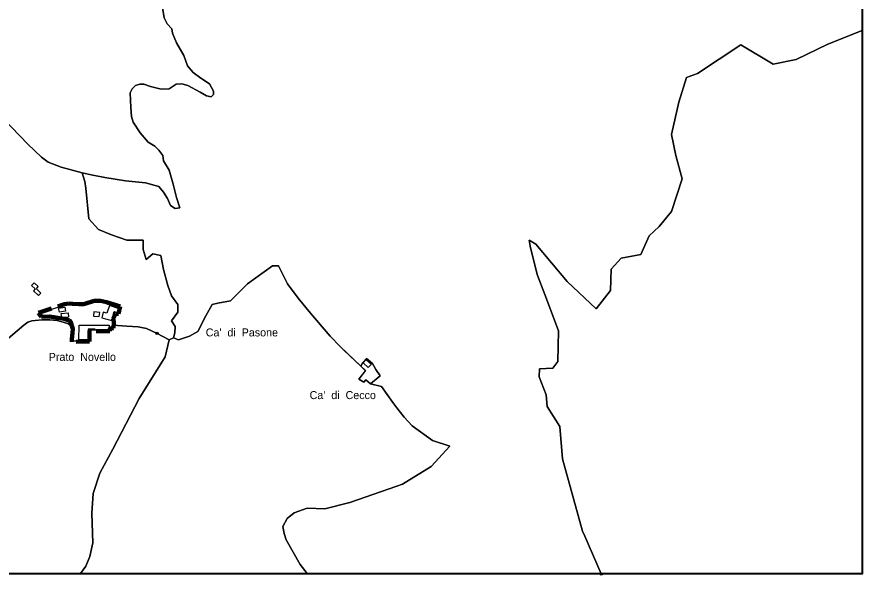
# Model space of a CAD drawing. Extents: x 650071 to 653841, y 889105 to 891996.
# Drawn here: x 652784 to 653840, y 889105 to 889802 of the extents above; entities that cross this region are included whole.
import ezdxf
from ezdxf.enums import TextEntityAlignment as Align

# ---------------------------------------------------------------- set-up
doc = ezdxf.new("R2010")
doc.units = 0
doc.header["$LTSCALE"] = 5.6
doc.header["$PDMODE"] = 32
doc.header["$PDSIZE"] = 2.8
doc.linetypes.add('MEDIUM_DASHED', pattern=[4.5, 3, -1.5])
for name, color, linetype, lineweight in [('1', 7, 'Continuous', 25), ('2', 7, 'Continuous', 25), ('35', 7, 'Continuous', 25), ('36', 7, 'Continuous', 25), ('6', 7, 'Continuous', 25), ('61', 7, 'Continuous', 35), ('7', 7, 'MEDIUM_DASHED', 100)]:
    doc.layers.add(name, color=color, linetype=linetype, lineweight=lineweight)
doc.layers.add('60', color=7, linetype='Continuous')

msp = doc.modelspace()

# ---------------------------------------------------------------- linework, layer by layer
at = {"layer": '1'}
for points in [[(652854.92, 889413.09), (652852.46, 889422.17), (652849.9, 889423.11), (652843.35, 889425.16), (652835.15, 889427.33), (652825.43, 889428.54), (652815.35, 889428.54), (652812.36, 889431.84), (652840.29, 889440.76), (652842.54, 889441.6), (652847.74, 889442.61), (652852.94, 889442.61), (652860.92, 889441.94), (652867.86, 889441.6)], [(652867.86, 889441.6), (652873.74, 889443.94), (652879.7, 889445.96), (652886.88, 889445.97), (652897.62, 889444)], [(652897.62, 889444), (652912.14, 889438.34), (652909.99, 889432.14), (652905.88, 889433.32), (652903.37, 889423.87), (652903.71, 889421.52), (652903.71, 889413.37), (652899.05, 889413.69), (652899.33, 889410.11), (652873.53, 889410.76), (652873.62, 889397.41)], [(652873.62, 889397.41), (652853.56, 889396.84), (652854.54, 889407.13), (652854.92, 889413.09)]]:
    msp.add_lwpolyline(points, dxfattribs=at)
for points in [[(652891.87, 889432.84), (652890.03, 889426.1), (652902.46, 889422.55), (652905.63, 889433.9), (652910.52, 889432.65), (652911.92, 889437.25), (652899.66, 889441.25), (652896.38, 889431.53)], [(652843.78, 889439.28), (652844.61, 889434.19), (652837.05, 889433.04), (652836.15, 889438.09)], [(652839.52, 889431.45), (652848.14, 889431.95), (652848.63, 889426.8), (652840.02, 889426.5)], [(652887.51, 889432.72), (652880.02, 889433.53), (652879.61, 889428.16), (652887, 889427.43)], [(652861.46, 889398.5), (652861.7, 889416.6), (652899.12, 889416.83), (652899.06, 889410.32), (652881.71, 889410.32), (652881.7, 889411.59), (652873.2, 889411.59), (652873.11, 889398.27)]]:
    msp.add_lwpolyline(points, close=True, dxfattribs=at)
for p in [(652897.62, 889444), (652873.62, 889397.41)]:
    msp.add_point(p, dxfattribs=at)
at = {"layer": '2'}
for points in [[(653220.8, 889374.93), (653216.05, 889370.18), (653213.55, 889365.67), (653219.55, 889359.92), (653211.05, 889349.42), (653217.3, 889345.41), (653219.8, 889348.41), (653225.8, 889343.41), (653237.8, 889353.42), (653232.55, 889361.42), (653228.3, 889368.93)], [(653216.42, 889369.6), (653220.33, 889373.91), (653226.98, 889368.12), (653222.96, 889363.68)]]:
    msp.add_lwpolyline(points, close=True, dxfattribs=at)
at = {"layer": '35'}
for points in [[(652979.78, 889400.93), (652981.3, 889407.01), (652981.75, 889415.02), (652977.32, 889421.98), (652985.03, 889432.92), (652985.07, 889442.41), (652977.26, 889453.44), (652972.66, 889466.17), (652966.95, 889486.4), (652963.82, 889503.67), (652953.92, 889505.79), (652945.44, 889498.72), (652941.9, 889511.26), (652941.55, 889522.94), (652921.29, 889522.7), (652902.3, 889529.51), (652885.96, 889536.22), (652874.02, 889549.47), (652870.14, 889587.85), (652869.08, 889596.19), (652867.34, 889601.61), (652865.64, 889606.92), (652839.37, 889614.13), (652823.01, 889620.44), (652814.61, 889626.6), (652797.51, 889642.88), (652777.09, 889664.15)], [(652772.99, 889399.89), (652784.2, 889409.56), (652792.81, 889416.78), (652797.7, 889420.62), (652802.59, 889421.98), (652807.01, 889422.65), (652815.62, 889423.56), (652825.16, 889423.56), (652834.24, 889422.43), (652841.92, 889420.4), (652848.43, 889418.36), (652854.91, 889413.08), (652854.94, 889413.11), (652854.56, 889407.15), (652853.56, 889396.84), (652873.64, 889397.43), (652873.53, 889410.76), (652899.33, 889410.11), (652899.07, 889413.71), (652903.73, 889413.39), (652903.74, 889416.54)], [(652903.74, 889416.54), (652921.24, 889415.65), (652935.52, 889414.72), (652945.82, 889412.61), (652959.16, 889406.52)], [(652959.16, 889406.52), (652974.27, 889398.52), (652979.78, 889400.92)]]:
    msp.add_lwpolyline(points, dxfattribs=at)
msp.add_point((652959.16, 889406.52), dxfattribs=at)
at = {"layer": '36'}
msp.add_line((652287.74, 889106.5), (652863.29, 889106.49), dxfattribs=at)
for points in [[(653490.64, 889159.46), (653465.43, 889249.71), (653462.06, 889290.08), (653446.37, 889315.3), (653445.25, 889329.88), (653436.29, 889352.3), (653436.85, 889362.39), (653453.66, 889362.95), (653459.82, 889371.36), (653460.38, 889409.48), (653443.57, 889454.89), (653434.05, 889480.12), (653425.09, 889515.44), (653423.97, 889522.74), (653432.37, 889517.69), (653471.58, 889471.16), (653507.44, 889436.97), (653525.37, 889459.96), (653526.49, 889486.86), (653538.81, 889500.32), (653563.46, 889504.8), (653573.63, 889528.13), (653586.24, 889540.12), (653601.68, 889558.73), (653614.99, 889599.54), (653607.15, 889628.69), (653601.55, 889655.04), (653610.74, 889695.06), (653620.28, 889725.89), (653634.21, 889731.03), (653688.5, 889767), (653728.85, 889742.78), (653757.46, 889748.65), (653797.07, 889767.74), (653839.8, 889784.85), (653839.8, 890111.65)], [(652965.37, 889816.12), (652967.83, 889800.54), (652971.6, 889793.18), (652977.45, 889786.75), (652978.59, 889781.46), (652983.31, 889769.37)], [(652977.45, 889786.75), (652971.6, 889793.18), (652967.83, 889800.54), (652965.37, 889816.12)], [(652992.37, 889753.69), (652983.31, 889769.37), (652978.59, 889781.46), (652977.45, 889786.75)], [(653839.8, 889784.85), (653797.07, 889767.74), (653757.46, 889748.65), (653728.85, 889742.78), (653688.5, 889767), (653634.21, 889731.03), (653620.28, 889725.89), (653610.74, 889695.06), (653601.55, 889655.04), (653607.15, 889628.69), (653614.99, 889599.54), (653601.68, 889558.73), (653586.24, 889540.12), (653573.63, 889528.13), (653563.46, 889504.8), (653538.81, 889500.32), (653526.49, 889486.86), (653525.37, 889459.96), (653507.44, 889436.97), (653471.58, 889471.16), (653432.37, 889517.69), (653423.97, 889522.74), (653425.09, 889515.44), (653434.05, 889480.12), (653443.57, 889454.89), (653460.38, 889409.48), (653459.82, 889371.36), (653453.66, 889362.95), (653436.85, 889362.39), (653436.29, 889352.3), (653445.25, 889329.88), (653446.37, 889315.3), (653462.06, 889290.08), (653465.43, 889249.71)], [(653513.96, 889106.04), (653839.8, 889106.04), (653839.8, 889784.85)], [(652983.31, 889769.37), (652992.37, 889753.69), (652997.09, 889740.66), (653004.26, 889732.16), (653013.71, 889724.98)], [(653004.26, 889732.16), (652997.09, 889740.66), (652992.37, 889753.69)], [(653029.76, 889709.11), (653024.56, 889718.09), (653013.71, 889724.98), (653004.26, 889732.16)], [(653013.71, 889724.98), (653024.56, 889718.09), (653029.76, 889709.11), (653029.42, 889704.7)], [(652942.56, 889717.7), (652937.58, 889717.83), (652932.07, 889716.12), (652928, 889711.79), (652925.37, 889706.67)], [(652925.37, 889706.67), (652928, 889711.79), (652932.07, 889716.12), (652937.58, 889717.83), (652942.56, 889717.7), (652951.03, 889714.97), (652959.15, 889712.89), (652964.44, 889711.38), (652974.44, 889711.75)], [(652974.44, 889711.75), (652970.1, 889711.57), (652964.44, 889711.38), (652959.15, 889712.89), (652951.03, 889714.97), (652942.56, 889717.7)], [(653012.96, 889707.79), (652997.66, 889716.1), (652990.06, 889718.22), (652982.84, 889717.7), (652974.44, 889711.75)], [(652974.44, 889711.75), (652982.84, 889717.7), (652990.06, 889718.22), (652997.66, 889716.1)], [(652997.66, 889716.1), (653012.96, 889707.79), (653020.76, 889703.25), (653026.79, 889701.94), (653029.42, 889704.7), (653029.76, 889709.11)], [(652925.37, 889706.67), (652926.3, 889688.71), (652927.05, 889677.37), (652929.4, 889670.15)], [(652927.05, 889677.37), (652926.3, 889688.71), (652925.37, 889706.67)], [(653029.42, 889704.7), (653026.79, 889701.94), (653020.76, 889703.25), (653012.96, 889707.79)], [(652687.03, 889628.56), (652693.04, 889632.01), (652703.99, 889640.27), (652724.26, 889656.34), (652742.42, 889669.71), (652750.52, 889674.66), (652756.38, 889676.17), (652762.98, 889676.17), (652768.53, 889672.56), (652777.09, 889664.15), (652797.51, 889642.88), (652814.61, 889626.6), (652823.01, 889620.44), (652839.37, 889614.13), (652865.64, 889606.92)], [(652948.02, 889645.16), (652938.03, 889656.97), (652929.4, 889670.15), (652927.05, 889677.37)], [(652929.4, 889670.15), (652938.03, 889656.97), (652948.02, 889645.16), (652956.19, 889640.16), (652961.18, 889635.16)], [(652961.18, 889635.16), (652956.19, 889640.16), (652948.02, 889645.16)], [(652961.18, 889635.16), (652966.18, 889628.8), (652967.08, 889621.99), (652974.35, 889610.18), (652979.34, 889592.91), (652983.43, 889576.1), (652987.51, 889563.38), (652981.61, 889562.47), (652975.71, 889566.11), (652972.08, 889574.74), (652967.08, 889582.92)], [(652974.35, 889610.18), (652967.08, 889621.99), (652966.18, 889628.8), (652961.18, 889635.16)], [(652975.71, 889566.11), (652981.61, 889562.47), (652987.51, 889563.38), (652983.43, 889576.1), (652979.34, 889592.91), (652974.35, 889610.18)], [(652919.87, 889597), (652894.07, 889601.08), (652876.74, 889604.27), (652865.64, 889606.92), (652869.08, 889596.18), (652870.14, 889587.85), (652874.02, 889549.47), (652885.96, 889536.21), (652902.3, 889529.5), (652921.29, 889522.69), (652941.55, 889522.94), (652941.9, 889511.26), (652945.44, 889498.72), (652953.92, 889505.79), (652963.82, 889503.67), (652966.95, 889486.39), (652972.66, 889466.17), (652977.26, 889453.44), (652985.07, 889442.41)], [(652865.64, 889606.92), (652876.74, 889604.27), (652894.07, 889601.08), (652919.87, 889597), (652944.84, 889594.28)], [(652967.08, 889582.92), (652961.18, 889589.73), (652944.84, 889594.28), (652919.87, 889597)], [(652944.84, 889594.28), (652961.18, 889589.73), (652967.08, 889582.92), (652972.08, 889574.74), (652975.71, 889566.11)], [(653027.95, 889442.53), (653035.13, 889444.09), (653051.05, 889447.22), (653071.97, 889468.15), (653103.51, 889490.95), (653110.76, 889490.77)], [(653110.76, 889490.77), (653103.51, 889490.95), (653071.97, 889468.15), (653051.05, 889447.22)], [(653121.97, 889468.35), (653114.89, 889482.4), (653110.76, 889490.77)], [(653110.76, 889490.77), (653114.89, 889482.4), (653121.97, 889468.35)], [(653150.86, 889431.76), (653135.53, 889450.64), (653121.97, 889468.35)], [(653121.97, 889468.35), (653135.53, 889450.64), (653150.86, 889431.76), (653175.43, 889403.07)], [(652985.07, 889442.41), (652985.03, 889432.92), (652977.32, 889421.98)], [(652979.78, 889400.92), (652985.8, 889398.48), (652999.54, 889403.16), (653010.16, 889408.79), (653019.83, 889428.47), (653027.95, 889442.53)], [(653051.05, 889447.22), (653035.13, 889444.09), (653027.95, 889442.53), (653019.83, 889428.47), (653010.16, 889408.79), (652999.54, 889403.16)], [(653253.53, 889319.98), (653239.43, 889340.18), (653225.8, 889343.36), (653219.8, 889348.36), (653217.32, 889345.39), (653217.3, 889345.41), (653211.08, 889349.41), (653219.55, 889359.87), (653213.55, 889365.62), (653192.73, 889385.04), (653188.23, 889389.73), (653175.43, 889403.07), (653150.86, 889431.76)], [(652863.29, 889106.49), (652869.94, 889115.87), (652875.13, 889127.82), (652878.73, 889145.06), (652877.7, 889182.15), (652879.16, 889206.37), (652887.58, 889231.88), (652903.94, 889261.73), (652936.66, 889325.03), (652969.38, 889377.26), (652974.27, 889398.52), (652959.16, 889406.52), (652945.82, 889412.61), (652935.52, 889414.72), (652921.24, 889415.65), (652903.74, 889416.54), (652903.73, 889413.39), (652899.07, 889413.71), (652899.33, 889410.11), (652873.53, 889410.76), (652873.64, 889397.43), (652853.56, 889396.84), (652854.56, 889407.15), (652854.94, 889413.11), (652854.91, 889413.08), (652848.43, 889418.36), (652841.92, 889420.4), (652834.24, 889422.43), (652825.16, 889423.56), (652815.62, 889423.56), (652807.01, 889422.65), (652802.59, 889421.98), (652797.7, 889420.62), (652792.81, 889416.78), (652784.2, 889409.56), (652772.99, 889399.89)], [(652977.32, 889421.98), (652981.75, 889415.01), (652981.3, 889407), (652979.78, 889400.92)], [(652999.54, 889403.16), (652985.8, 889398.48), (652979.78, 889400.92), (652974.27, 889398.52), (652969.38, 889377.26), (652936.66, 889325.03), (652903.94, 889261.73), (652887.58, 889231.88)], [(653175.43, 889403.07), (653188.23, 889389.73), (653213.55, 889365.62), (653216.05, 889370.13), (653220.8, 889374.88), (653228.3, 889368.88), (653232.55, 889361.37), (653237.8, 889353.37), (653225.8, 889343.36)], [(653225.8, 889343.36), (653239.43, 889340.18), (653253.53, 889319.98), (653258.53, 889313.6), (653267.63, 889302.02), (653277.88, 889291.12)], [(653324.66, 889265.47), (653303.19, 889272.52), (653277.88, 889291.12), (653267.63, 889302.02), (653258.53, 889313.6), (653253.53, 889319.98)], [(653277.88, 889291.12), (653303.19, 889272.52), (653324.66, 889265.47)], [(653324.66, 889265.47), (653301.71, 889240.43), (653265.71, 889218.02), (653258.54, 889215.53), (653258.53, 889215.53)], [(653258.54, 889215.53), (653265.71, 889218.02), (653301.71, 889240.43), (653324.66, 889265.47)], [(653465.43, 889249.71), (653490.64, 889159.46), (653493.28, 889153.4), (653513.96, 889106.04)], [(652887.58, 889231.88), (652879.16, 889206.37), (652877.7, 889182.15), (652878.73, 889145.06)], [(653116.4, 889165.43), (653121.53, 889175.37), (653130.5, 889182.42), (653146.52, 889188.2), (653168.63, 889187.55), (653200.03, 889195.25), (653258.53, 889215.53), (653258.54, 889215.53)], [(653258.53, 889215.53), (653200.03, 889195.25), (653168.63, 889187.55), (653146.52, 889188.2), (653130.5, 889182.42)], [(653130.5, 889182.42), (653121.53, 889175.37), (653116.4, 889165.43)], [(653120.58, 889148.75), (653117.77, 889156.52), (653116.4, 889165.43)], [(653116.4, 889165.43), (653117.77, 889156.52), (653120.58, 889148.75), (653137.87, 889117.98), (653146.63, 889106.49), (653258.53, 889106.49), (653513.96, 889106.04), (653493.28, 889153.4), (653490.64, 889159.46)], [(652878.73, 889145.06), (652875.13, 889127.82), (652869.94, 889115.87), (652863.29, 889106.49), (653146.63, 889106.49), (653137.87, 889117.98), (653120.58, 889148.75)]]:
    msp.add_lwpolyline(points, dxfattribs=at)
msp.add_point((653513.96, 889106.04), dxfattribs=at)
at = {"layer": '6'}
msp.add_lwpolyline([(652804.69, 889459.6), (652810.91, 889453.69), (652814.07, 889456.85), (652808.32, 889462.26), (652810.79, 889464.92), (652805.62, 889469.79), (652802.39, 889466.37), (652806.78, 889462.23)], close=True, dxfattribs=at)
at = {"layer": '61', "lineweight": 40}
msp.add_lwpolyline([(653839.81, 891995.66), (653839.8, 889106.04), (652174.44, 889106.04), (652174.45, 891995.66)], close=True, dxfattribs=at)
at = {"layer": '7'}
msp.add_lwpolyline([(652853.85, 889412.05), (652851.15, 889421.42), (652849.15, 889422.68), (652842.97, 889424.44), (652832.59, 889426.49), (652824.57, 889427.5), (652814.68, 889427.12), (652811.18, 889432.24), (652840.83, 889442.1), (652843.63, 889442.96), (652848.83, 889443.97), (652853.65, 889443.54), (652861.5, 889442.93), (652867.64, 889442.8), (652880.39, 889447.31), (652888.26, 889447.12), (652895.76, 889445.43), (652907.95, 889441.68), (652913.01, 889439.99), (652910.88, 889430.94), (652907.27, 889431.09), (652904.45, 889424.81), (652904.98, 889420.95), (652904.85, 889412.92), (652900.07, 889412.61), (652899.92, 889409.08), (652874.77, 889409.61), (652874.77, 889396.29), (652852.49, 889395.74), (652852.78, 889399.31), (652853.47, 889407.11)], close=True, dxfattribs=at)

# ---------------------------------------------------------------- texts
at = {"layer": '60'}
for s, p in [("Ca'  di  Pasone", (653065.05, 889402.69)), ('Prato  Novello', (652865.75, 889372.07)), ("Ca'  di  Cecco", (653191.09, 889324.41))]:
    msp.add_text(s, height=10, dxfattribs=at).set_placement(p, align=Align.CENTER)

doc.saveas('drawing.dxf')
